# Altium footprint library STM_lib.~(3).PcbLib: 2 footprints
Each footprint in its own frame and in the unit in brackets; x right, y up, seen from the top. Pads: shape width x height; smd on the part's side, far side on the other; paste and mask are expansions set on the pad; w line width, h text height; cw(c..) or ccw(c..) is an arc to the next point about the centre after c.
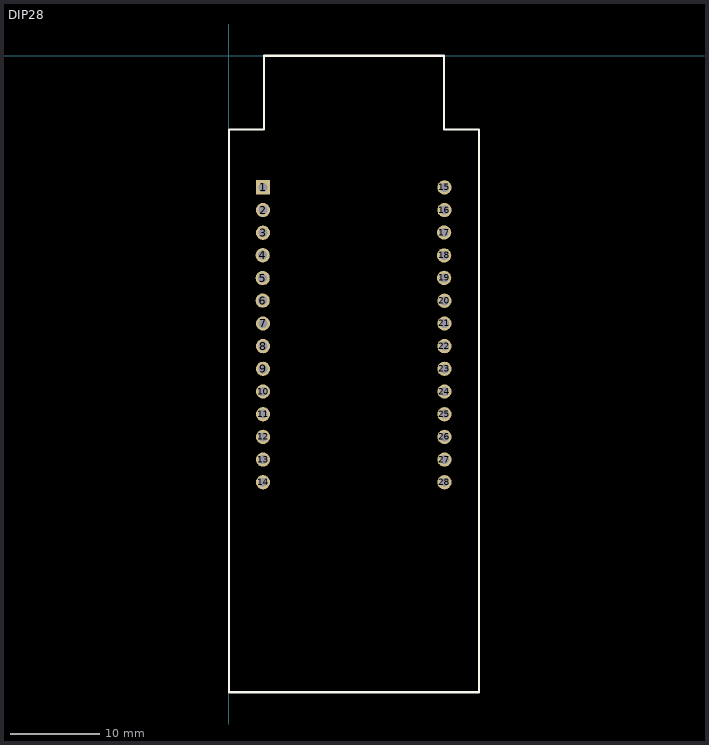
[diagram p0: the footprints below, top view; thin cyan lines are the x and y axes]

## DIP28 [mm]
pads (28):
  rect 1.6x1.6 hole 1: 1(3.81,-14.732)
  round 1.6 hole 1: 2(3.81,-17.272) 3(3.81,-19.812) 4(3.772,-22.328) 5(3.772,-24.889) 6(3.772,-27.408) 7(3.81,-29.972) 8(3.81,-32.512) 9(3.81,-35.052) 10(3.81,-37.592) 11(3.81,-40.132) 12(3.81,-42.672) 13(3.81,-45.212) 14(3.81,-47.752) 15(24.13,-14.732) 16(24.13,-17.272) 17(24.092,-19.788) 18(24.092,-22.349) 19(24.092,-24.868) 20(24.13,-27.432) 21(24.13,-29.972) 22(24.13,-32.512) 23(24.13,-35.052) 24(24.13,-37.592) 25(24.13,-40.132) 26(24.13,-42.672) 27(24.13,-45.212) 28(24.13,-47.752)
Top Overlay:
  lines w0.254: 0,-71.26 28,-71.26 28,-8.26 24.068,-8.26 24.068,0 3.932,0 3.932,-8.26 0,-8.26 0,-71.26

## PCBComponent_1 [mm]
